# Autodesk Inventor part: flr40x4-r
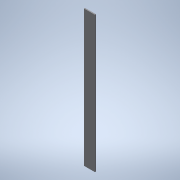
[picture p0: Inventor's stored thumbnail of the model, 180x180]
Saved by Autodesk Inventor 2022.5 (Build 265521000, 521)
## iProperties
Created: 2016-12
Part Number: flr40x4-r
Material: 一般
Document SubType Name: Modeling
Designer: imaocorp
Density: 1 g/cm^3
Appearance: 既定
Author: imaocorp
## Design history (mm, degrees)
node "flr40x4-r.x_t1"
node "flr40x4-r"
node "Base1"
